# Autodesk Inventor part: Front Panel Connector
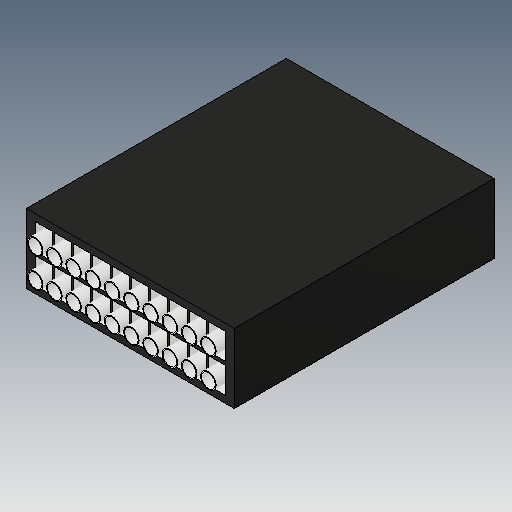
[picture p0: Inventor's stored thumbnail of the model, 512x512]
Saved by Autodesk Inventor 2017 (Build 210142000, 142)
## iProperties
Created: 2005-12
Part Number: Front Panel Connector
Material: Generic
Document SubType Name: Modeling
Designer: DanielSeverino
Density: 1 g/cm^3
Appearance: Default
Author: DanielSeverino
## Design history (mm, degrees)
feature "Solid1"
feature "Solid1:1"
feature "Solid1:2"
feature "Solid1:3"
feature "Solid1:4"
feature "Solid1:5"
feature "Solid1:6"
feature "Solid1:7"
feature "Solid1:8"
feature "Solid1:9"
feature "Solid1:10"
feature "Solid1:11"
feature "Solid1:12"
feature "Solid1:13"
feature "Solid1:14"
feature "Solid1:15"
feature "Solid1:16"
feature "Solid1:17"
feature "Solid1:18"
feature "Solid1:19"
feature "Solid1:20"
body "Solid2"
body "Solid3"
body "Solid4"
body "Solid5"
body "Solid6"
body "Solid7"
body "Solid8"
body "Solid9"
body "Solid10"
body "Solid11"
body "Solid12"
body "Solid13"
body "Solid14"
body "Solid15"
body "Solid16"
body "Solid17"
body "Solid18"
body "Solid19"
body "Solid20"
body "Solid21"
body "Solid22"
